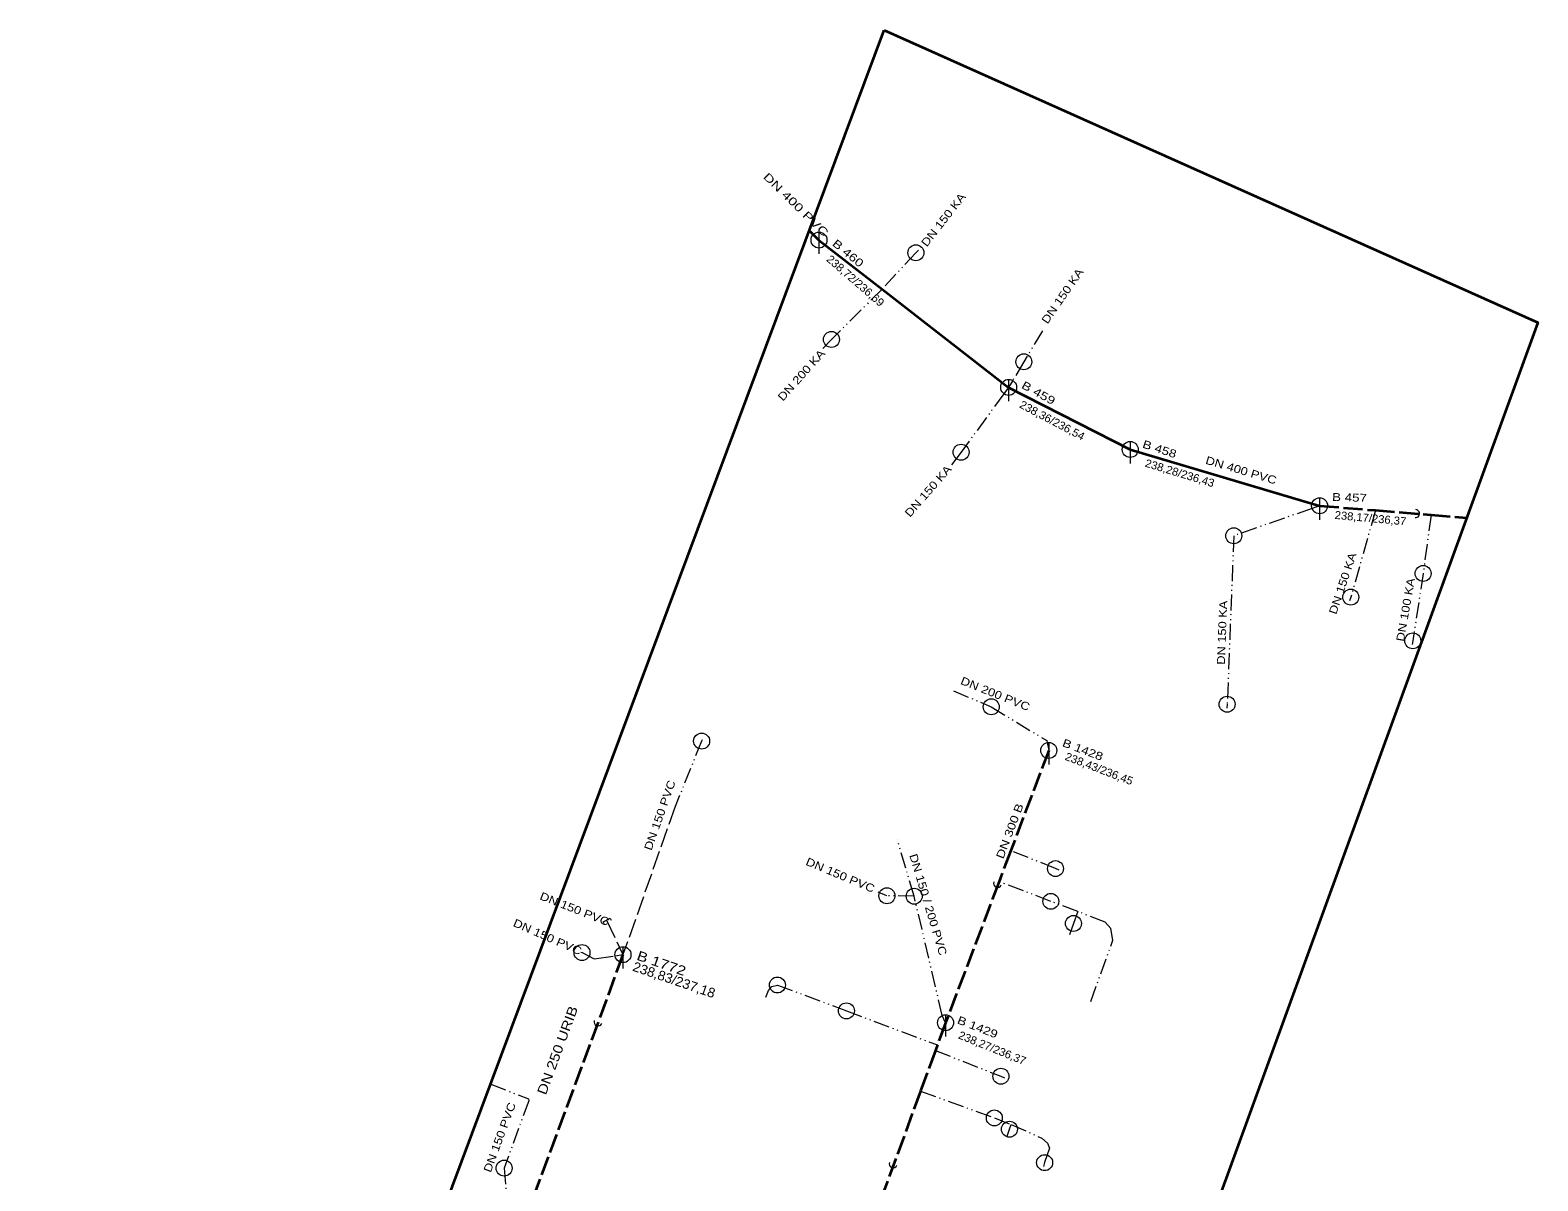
# Model space of a CAD drawing. Extents: x -644344 to -644155, y -1042439 to -1042139.
# Drawn here: x -644344 to -644155.2, y -1042282.7 to -1042138.6 of the extents above; entities that cross this region are included whole.
import ezdxf
from ezdxf.enums import TextEntityAlignment as Align

# ---------------------------------------------------------------- set-up
doc = ezdxf.new("R2010")
doc.units = 0
doc.header["$LTSCALE"] = 0.4
doc.linetypes.add('DASH_DOUBLE_DOT', pattern=[9.2, 5, -1.2, 0.3, -1.2, 0.3, -1.2])
doc.linetypes.add('LONG_DASHED', pattern=[7.5, 6, -1.5])
for name, color, linetype, lineweight in [('10', 7, 'Continuous', 13), ('14', 7, 'Continuous', 13), ('23', 7, 'LONG_DASHED', 35), ('24', 7, 'DASH_DOUBLE_DOT', 35), ('33', 7, 'LONG_DASHED', 13), ('34', 7, 'DASH_DOUBLE_DOT', 13), ('63', 7, 'Continuous', 35)]:
    doc.layers.add(name, color=color, linetype=linetype, lineweight=lineweight)
doc.layers.add('29', color=7, linetype='Continuous')
doc.layers.add('39', color=7, linetype='Continuous')

msp = doc.modelspace()

# ---------------------------------------------------------------- linework, layer by layer
at = {"layer": '10'}
for p, q in [((-644245.19, -1042163.89), (-644245.19, -1042166.638)), ((-644221.44, -1042182.34), (-644221.44, -1042185.088)), ((-644206.22, -1042190.12), (-644206.22, -1042192.868)), ((-644182.5, -1042197.17), (-644182.5, -1042199.918)), ((-644216.42, -1042227.81), (-644216.42, -1042230.558)), ((-644272.236, -1042250.265), (-644271.332, -1042249.837)), ((-644272.236, -1042250.265), (-644272.129, -1042250.491)), ((-644271.332, -1042249.837), (-644271.225, -1042250.064)), ((-644269.735, -1042253.389), (-644269.735, -1042256.137)), ((-644229.34, -1042261.91), (-644229.34, -1042264.658))]:
    msp.add_line(p, q, dxfattribs=at)
for centre, radius in [((-644245.1897, -1042164.8903), 1.0002), ((-644233.0597, -1042166.4802), 1), ((-644243.6297, -1042177.3402), 1), ((-644219.5397, -1042180.1402), 1), ((-644221.4397, -1042183.3403), 1.0002), ((-644206.2197, -1042191.1203), 1.0002), ((-644227.3997, -1042191.4602), 1), ((-644182.4997, -1042198.1703), 1.0002), ((-644193.2497, -1042201.9302), 1), ((-644169.5397, -1042206.6502), 1), ((-644178.5997, -1042209.6152), 1), ((-644170.8347, -1042215.0862), 1), ((-644223.6199, -1042223.3503), 1), ((-644194.0807, -1042223.0322), 1), ((-644259.8848, -1042227.6427), 1), ((-644216.4197, -1042228.8103), 1.0002), ((-644215.5761, -1042243.6141), 1), ((-644236.6824, -1042247.0103), 1), ((-644233.2701, -1042247.0653), 1), ((-644216.1599, -1042247.7108), 1), ((-644213.3228, -1042250.4847), 1), ((-644274.8648, -1042254.1271), 1), ((-644269.7347, -1042254.3893), 1.0002), ((-644250.4032, -1042258.1907), 1), ((-644241.7582, -1042261.4288), 1), ((-644229.3397, -1042262.9103), 1.0002), ((-644222.4143, -1042269.6181), 1), ((-644223.2327, -1042274.8417), 1), ((-644221.3384, -1042276.2486), 1), ((-644284.6162, -1042281.1213), 1), ((-644216.9333, -1042280.4388), 1)]:
    msp.add_circle(centre, radius, dxfattribs=at)
at = {"layer": '14'}
for centre, start, end in [((-644170.503, -1042199.1546), 265.31037, 85.31037), ((-644222.8352, -1042245.4608), 159.04245, 339.04245), ((-644272.8564, -1042262.8218), 159.69182, 339.69182), ((-644235.9086, -1042280.5865), 160.12948, 340.12948)]:
    msp.add_arc(centre, 0.5, start, end, dxfattribs=at)
at = {"layer": '23'}
for p, q in [((-644237.293, -1042171.025), (-644237.285, -1042171.031)), ((-644222.646, -1042245.242), (-644229.34, -1042262.91)), ((-644269.735, -1042254.389), (-644281.51, -1042286.207)), ((-644229.34, -1042262.91), (-644230.361, -1042265.698)), ((-644230.361, -1042265.698), (-644230.612, -1042266.383))]:
    msp.add_line(p, q, dxfattribs=at)
for points in [[(-644182.5, -1042198.17), (-644175.523, -1042198.742), (-644168.547, -1042199.315), (-644164.085, -1042199.681)], [(-644216.42, -1042228.81), (-644221.176, -1042241.362), (-644221.176, -1042241.362)], [(-644221.176, -1042241.362), (-644222.646, -1042245.242), (-644222.646, -1042245.242)], [(-644230.612, -1042266.383), (-644232.478, -1042271.477), (-644232.478, -1042271.477), (-644242.61, -1042299.13)]]:
    msp.add_lwpolyline(points, dxfattribs=at)
at = {"layer": '24', "linetype": 'Continuous'}
msp.add_line((-644237.285, -1042171.031), (-644221.44, -1042183.34), dxfattribs=at)
for points in [[(-644246.389, -1042163.721), (-644245.19, -1042164.89), (-644237.293, -1042171.025)], [(-644221.44, -1042183.34), (-644206.22, -1042191.12), (-644182.5, -1042198.17)]]:
    msp.add_lwpolyline(points, dxfattribs=at)
at = {"layer": '33'}
for p, q in [((-644263.191, -1042235.818), (-644269.403, -1042253.446)), ((-644271.784, -1042250.051), (-644270.162, -1042253.485)), ((-644273.335, -1042254.895), (-644270.725, -1042254.528)), ((-644270.725, -1042254.528), (-644269.735, -1042254.389)), ((-644270.162, -1042253.485), (-644269.735, -1042254.389)), ((-644269.403, -1042253.446), (-644269.735, -1042254.389))]:
    msp.add_line(p, q, dxfattribs=at)
at = {"layer": '34'}
for p, q in [((-644233.06, -1042166.48), (-644237.285, -1042171.031)), ((-644237.293, -1042171.025), (-644243.63, -1042177.34)), ((-644243.63, -1042177.34), (-644244.703, -1042178.479)), ((-644219.54, -1042180.14), (-644220.929, -1042182.48)), ((-644222.034, -1042184.145), (-644227.4, -1042191.46)), ((-644227.4, -1042191.46), (-644228.708, -1042193.187)), ((-644183.444, -1042198.5), (-644193.25, -1042201.93)), ((-644182.5, -1042198.17), (-644183.444, -1042198.5)), ((-644175.523, -1042198.742), (-644178.6, -1042209.615)), ((-644168.547, -1042199.315), (-644169.54, -1042206.65)), ((-644193.25, -1042201.93), (-644194.081, -1042223.032)), ((-644169.54, -1042206.65), (-644170.835, -1042215.086)), ((-644178.6, -1042209.615), (-644178.75, -1042210.091)), ((-644170.835, -1042215.086), (-644170.904, -1042215.535)), ((-644194.081, -1042223.032), (-644194.101, -1042223.532)), ((-644259.818, -1042227.477), (-644259.885, -1042227.643)), ((-644216.624, -1042227.831), (-644216.42, -1042228.81)), ((-644233.27, -1042247.065), (-644235.386, -1042240.006)), ((-644215.576, -1042243.614), (-644221.176, -1042241.362)), ((-644215.112, -1042243.801), (-644215.576, -1042243.614)), ((-644236.682, -1042247.01), (-644237.795, -1042246.544)), ((-644216.16, -1042247.711), (-644222.646, -1042245.242)), ((-644233.27, -1042247.065), (-644236.682, -1042247.01)), ((-644229.759, -1042262.002), (-644233.27, -1042247.065)), ((-644212.784, -1042248.997), (-644216.16, -1042247.711)), ((-644213.323, -1042250.485), (-644213.831, -1042251.888)), ((-644212.784, -1042248.997), (-644213.323, -1042250.485)), ((-644275.002, -1042254.058), (-644274.865, -1042254.127)), ((-644250.403, -1042258.191), (-644241.758, -1042261.429)), ((-644241.758, -1042261.429), (-644230.361, -1042265.698)), ((-644229.34, -1042262.91), (-644229.759, -1042262.002)), ((-644230.612, -1042266.383), (-644222.414, -1042269.618)), ((-644222.414, -1042269.618), (-644221.949, -1042269.802)), ((-644221.636, -1042277.11), (-644221.339, -1042276.249)), ((-644221.339, -1042276.249), (-644221.14, -1042275.673))]:
    msp.add_line(p, q, dxfattribs=at)
for points in [[(-644232.736, -1042166.14), (-644233.06, -1042166.48), (-644233.06, -1042166.48)], [(-644217.217, -1042176.274), (-644219.54, -1042180.14), (-644219.54, -1042180.14)], [(-644220.929, -1042182.48), (-644221.44, -1042183.34), (-644222.034, -1042184.145)], [(-644228.337, -1042221.351), (-644223.62, -1042223.35), (-644223.62, -1042223.35)], [(-644223.62, -1042223.35), (-644216.676, -1042227.582), (-644216.624, -1042227.831)], [(-644259.885, -1042227.643), (-644263.191, -1042235.818), (-644263.191, -1042235.818)], [(-644211.165, -1042260.235), (-644208.399, -1042252.58), (-644208.646, -1042251.098), (-644209.338, -1042250.308), (-644212.784, -1042248.997)], [(-644274.865, -1042254.127), (-644273.335, -1042254.895), (-644273.335, -1042254.895)], [(-644251.831, -1042259.717), (-644251.519, -1042258.891), (-644251.109, -1042258.387), (-644250.403, -1042258.191), (-644250.403, -1042258.191)], [(-644286.3, -1042270.597), (-644281.579, -1042272.458), (-644281.534, -1042272.713), (-644284.616, -1042281.121), (-644284.616, -1042281.121)], [(-644232.478, -1042271.477), (-644223.233, -1042274.841), (-644221.14, -1042275.673)], [(-644221.14, -1042275.673), (-644217.267, -1042277.362), (-644216.595, -1042277.979), (-644216.335, -1042278.643), (-644216.933, -1042280.439), (-644217.091, -1042280.913)], [(-644284.616, -1042281.121), (-644284.126, -1042287.15), (-644284.126, -1042287.15)]]:
    msp.add_lwpolyline(points, dxfattribs=at)
at = {"layer": '63'}
msp.add_lwpolyline([(-644237.01, -1042138.605), (-644155.176, -1042175.215), (-644251.367, -1042439.381), (-644343.968, -1042425.024)], close=True, dxfattribs=at)

# ---------------------------------------------------------------- texts
at = {"layer": '29'}
for s, height, rotation, width, p in [('DN 400 PVC', 1, 315.723, 1.4, (-644248.4141, -1042160.8166)), ('238,72/236,69', 1, 319.119, 1.05, (-644240.9492, -1042170.3706)), ('238,36/236,54', 1, 332.045, 1.05, (-644216.2179, -1042187.9224)), ('DN 400 PVC', 1, 343.447, 1.2, (-644192.4694, -1042194.1973)), ('238,28/236,43', 1, 343.091, 1.05, (-644200.1584, -1042194.5533)), ('238,17/236,37', 1, 354.76, 1.05, (-644176.1777, -1042200.2187)), ('238,43/236,45', 1, 338.975, 1.05, (-644210.2914, -1042231.5673)), ('DN 300 B', 1, 69.304, 1.25, (-644220.8375, -1042239.0827)), ('238,83/237,18', 1.2, 341.202, 1.05, (-644263.5288, -1042258.1115)), ('DN 250 URIB', 1.2, 69.692, 1.2, (-644277.373, -1042266.5732)), ('238,27/236,37', 1, 337.9, 1.05, (-644223.6816, -1042266.5334))]:
    msp.add_text(s, height=height, rotation=rotation, dxfattribs=dict(at, width=width)).set_placement(p, align=Align.CENTER)
for s, height, rotation, width, p in [('B 460', 1, 320.306, 1.3, (-644243.613, -1042165.482)), ('B 459', 1, 331.032, 1.3, (-644219.931, -1042183.375)), ('B 458', 1, 341.826, 1.25, (-644204.766, -1042190.863)), ('B 457', 1, 358.288, 1.25, (-644180.953, -1042197.562)), ('B 1428', 1, 339.399, 1.25, (-644214.812, -1042228.256)), ('B 1772', 1.2, 340.993, 1.25, (-644268.108, -1042254.999)), ('B 1429', 1, 338.638, 1.25, (-644227.975, -1042262.967))]:
    msp.add_text(s, height=height, rotation=rotation, dxfattribs=dict(at, width=width)).set_placement(p)
at = {"layer": '39', "width": 1.2}
for s, rotation, p in [('DN 150 KA', 51.934, (-644229.2218, -1042162.6633)), ('DN 150 KA', 55.331, (-644214.2969, -1042172.1864)), ('DN 200 KA', 48.148, (-644247.0299, -1042182.1486)), ('DN 150 KA', 48.722, (-644231.1479, -1042196.6639)), ('DN 150 KA', 71.438, (-644179.1475, -1042208.0472)), ('DN 100 KA', 80.133, (-644171.2543, -1042211.2747)), ('DN 150 KA', 87.745, (-644194.216, -1042214.0837)), ('DN 200 PVC', 338.125, (-644223.3013, -1042222.1774)), ('DN 150 PVC', 70.589, (-644264.652, -1042237.0892)), ('DN 150 PVC', 337.282, (-644242.7091, -1042244.8817)), ('DN 150 / 200 PVC', 286.687, (-644231.9954, -1042248.2604)), ('DN 150 PVC', 338.422, (-644275.9729, -1042249.1253)), ('DN 150 PVC', 336.231, (-644279.3845, -1042252.6241)), ('DN 150 PVC', 69.869, (-644284.7136, -1042277.4351))]:
    msp.add_text(s, height=1, rotation=rotation, dxfattribs=at).set_placement(p, align=Align.CENTER)

doc.saveas('drawing.dxf')
